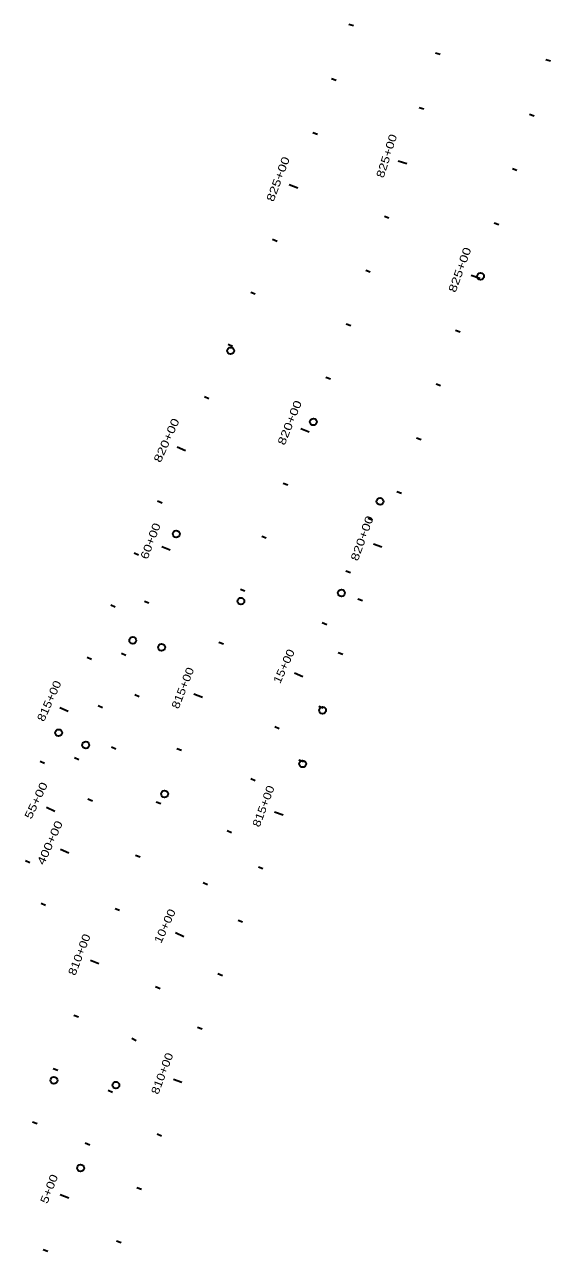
# Model space of a CAD drawing. Extents: x 2357892 to 2370172, y 6966790 to 6985499.
# Drawn here: x 2365397 to 2366317, y 6981138 to 6983284 of the extents above; entities that cross this region are included whole.
import ezdxf
from ezdxf.enums import TextEntityAlignment as Align

# ---------------------------------------------------------------- set-up
doc = ezdxf.new("R2010")
doc.units = 0
doc.header["$LTSCALE"] = 5.6
doc.layers.add('28', color=7, linetype='Continuous', lineweight=35)

msp = doc.modelspace()

# ---------------------------------------------------------------- linework, layer by layer
at = {"layer": '28'}
for p, q in [((2365972.504, 6983281.605), (2365964.385, 6983284.12)), ((2366124.2, 6983231.788), (2366116.031, 6983234.137)), ((2366317.341, 6983219.97), (2366309.172, 6983222.32)), ((2365941.948, 6983186.389), (2365933.881, 6983189.068)), ((2366095.827, 6983135.898), (2366087.695, 6983138.373)), ((2366288.852, 6983124.115), (2366280.726, 6983126.607)), ((2365909.475, 6983091.81), (2365901.464, 6983094.651)), ((2366065.982, 6983040.457), (2366050.749, 6983045.349)), ((2366258.695, 6983028.772), (2366250.614, 6983031.406)), ((2365875.098, 6982997.906), (2365860.13, 6983003.558)), ((2366034.673, 6982945.486), (2366026.621, 6982948.209)), ((2366226.879, 6982933.97), (2366218.844, 6982936.744)), ((2365838.832, 6982904.716), (2365830.942, 6982907.879)), ((2366001.906, 6982851.007), (2365993.897, 6982853.854)), ((2366193.414, 6982839.737), (2366178.38, 6982845.211)), ((2365800.69, 6982812.278), (2365792.866, 6982815.599)), ((2365967.689, 6982757.044), (2365959.725, 6982760.014)), ((2366159.197, 6982745.773), (2366151.21, 6982748.681)), ((2365760.688, 6982720.629), (2365752.933, 6982724.108)), ((2365932.031, 6982663.619), (2365924.113, 6982666.711)), ((2366124.98, 6982651.809), (2366116.993, 6982654.717)), ((2365719.621, 6982629.451), (2365711.871, 6982632.942)), ((2365894.968, 6982570.742), (2365880.137, 6982576.746)), ((2365678.548, 6982538.275), (2365663.96, 6982544.847)), ((2366090.763, 6982557.845), (2366082.776, 6982560.754)), ((2365857.444, 6982478.049), (2365849.566, 6982481.238)), ((2366056.546, 6982463.881), (2366048.559, 6982466.79)), ((2365637.475, 6982447.099), (2365629.725, 6982450.591)), ((2366005.979, 6982416.855), (2365998.09, 6982420.02)), ((2365819.921, 6982385.356), (2365812.042, 6982388.545)), ((2366022.329, 6982369.918), (2366007.295, 6982375.392)), ((2365596.402, 6982355.924), (2365588.652, 6982359.415)), ((2365651.754, 6982364.585), (2365636.8, 6982370.276)), ((2365967.125, 6982324.717), (2365959.352, 6982328.156)), ((2365782.398, 6982292.663), (2365774.519, 6982295.852)), ((2365555.329, 6982264.748), (2365547.579, 6982268.239)), ((2365614.563, 6982271.763), (2365606.73, 6982275.062)), ((2365988.112, 6982275.954), (2365980.125, 6982278.862)), ((2365925.681, 6982233.71), (2365917.955, 6982237.253)), ((2365745.008, 6982199.916), (2365737.118, 6982203.077)), ((2365574.291, 6982180.235), (2365566.541, 6982183.726)), ((2365953.895, 6982181.99), (2365945.908, 6982184.899)), ((2365514.256, 6982173.572), (2365506.506, 6982177.064)), ((2365884.003, 6982142.809), (2365869.459, 6982149.478)), ((2365597.627, 6982107.865), (2365589.877, 6982111.356)), ((2365708.017, 6982107.009), (2365693.139, 6982112.895)), ((2365473.183, 6982082.397), (2365458.594, 6982088.968)), ((2365533.218, 6982089.059), (2365525.468, 6982092.55)), ((2365919.678, 6982088.026), (2365911.691, 6982090.935)), ((2365842.325, 6982051.909), (2365834.598, 6982055.451)), ((2365556.553, 6982016.69), (2365548.804, 6982020.181)), ((2365671.432, 6982013.942), (2365663.514, 6982017.035)), ((2365431.829, 6981991.349), (2365424.116, 6981994.921)), ((2365492.081, 6981997.913), (2365484.348, 6982001.442)), ((2365884.891, 6981994.272), (2365876.942, 6981997.281)), ((2365800.646, 6981961.008), (2365792.92, 6981964.551)), ((2365515.48, 6981925.514), (2365507.73, 6981929.005)), ((2365635.246, 6981920.719), (2365627.317, 6981923.783)), ((2365449.762, 6981907.31), (2365435.325, 6981914.208)), ((2365849.448, 6981900.765), (2365834.486, 6981906.436)), ((2365758.968, 6981870.108), (2365751.242, 6981873.65)), ((2365474.407, 6981834.338), (2365459.819, 6981840.91)), ((2365405.864, 6981817.461), (2365398.26, 6981821.259)), ((2365599.194, 6981827.444), (2365591.266, 6981830.508)), ((2365814.003, 6981807.257), (2365806.055, 6981810.27)), ((2365717.29, 6981779.207), (2365709.563, 6981782.75)), ((2365433.334, 6981743.163), (2365425.584, 6981746.654)), ((2365563.143, 6981734.168), (2365555.215, 6981737.233)), ((2365778.558, 6981713.749), (2365770.61, 6981716.762)), ((2365675.612, 6981688.306), (2365661.068, 6981694.975)), ((2365527.092, 6981640.893), (2365512.167, 6981646.661)), ((2365743.113, 6981620.242), (2365735.165, 6981623.255)), ((2365633.934, 6981597.406), (2365626.207, 6981600.948)), ((2365491.04, 6981547.617), (2365483.112, 6981550.682)), ((2365707.669, 6981526.734), (2365699.721, 6981529.747)), ((2365592.255, 6981506.505), (2365584.529, 6981510.048)), ((2365454.989, 6981454.342), (2365447.06, 6981457.406)), ((2365672.224, 6981433.227), (2365657.263, 6981438.898)), ((2365550.61, 6981415.589), (2365542.866, 6981419.093)), ((2365418.802, 6981361.119), (2365410.885, 6981364.212)), ((2365510.989, 6981323.779), (2365503.127, 6981327.01)), ((2365636.779, 6981339.719), (2365628.831, 6981342.732)), ((2365474.069, 6981230.845), (2365459.181, 6981236.704)), ((2365601.335, 6981246.211), (2365593.386, 6981249.224)), ((2365565.89, 6981152.704), (2365557.942, 6981155.716)), ((2365437.451, 6981137.791), (2365429.541, 6981140.903))]:
    msp.add_line(p, q, dxfattribs=at)
for centre in [(2366194.885, 6982843.775), (2365757.41, 6982713.335), (2365902.369, 6982589.024), (2366018.989, 6982449.866), (2365662.378, 6982392.953), (2365951.376, 6982289.751), (2365775.448, 6982275.496), (2365586.275, 6982206.837), (2365636.765, 6982194.746), (2365918.4, 6982084.517), (2365456.378, 6982045.093), (2365503.785, 6982023.722), (2365883.552, 6981990.735), (2365641.963, 6981938.098), (2365448.29, 6981437.011), (2365556.595, 6981428.729), (2365494.901, 6981283.783)]:
    msp.add_circle(centre, 6, dxfattribs=at)

# ---------------------------------------------------------------- texts
for s, rotation, width, p in [('825+00', 72.195, 1.25, (2366037.155, 6983052.077)), ('825+00', 69.314, 1.3, (2365847.031, 6983011.329)), ('825+00', 69.991, 1.3, (2366165.158, 6982852.739)), ('820+00', 67.961, 1.3, (2365867.296, 6982585.001)), ('820+00', 65.749, 1.3, (2365651.579, 6982553.883)), ('820+00', 69.991, 1.3, (2365994.072, 6982382.921)), ('60+00', 69.166, 1.25, (2365623.728, 6982378.1)), ('15+00', 65.368, 1.2, (2365857.162, 6982158.647)), ('815+00', 68.415, 1.2, (2365680.211, 6982120.988)), ('815+00', 65.749, 1.2, (2365446.214, 6982098.005)), ('55+00', 64.462, 1.3, (2365423.232, 6981923.692)), ('815+00', 69.24, 1.2, (2365821.4, 6981914.234)), ('400+00', 65.749, 1.3, (2365447.438, 6981849.946)), ('10+00', 65.368, 1.2, (2365648.771, 6981704.145)), ('810+00', 68.868, 1.2, (2365499.152, 6981654.593)), ('810+00', 69.24, 1.2, (2365644.178, 6981446.696)), ('5+00', 68.519, 1.25, (2365446.231, 6981244.76))]:
    msp.add_text(s, height=14, rotation=rotation, dxfattribs=dict(at, width=width)).set_placement(p, align=Align.CENTER)

doc.saveas('drawing.dxf')
